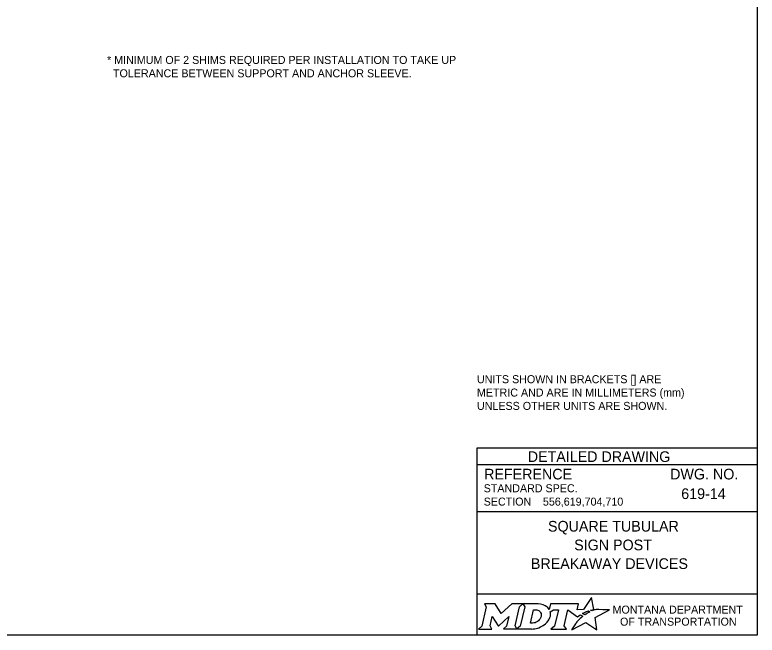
# Model space of a CAD drawing. Extents: x 49940 to 50043, y 49986 to 50011.
# Drawn here: x 50011.19 to 50016.75, y 49987.8 to 49992.45 of the extents above; entities that cross this region are included whole.
import ezdxf

# ---------------------------------------------------------------- set-up
doc = ezdxf.new("R2010")
doc.units = 0
for name, color, linetype in [('Default', 7, 'Continuous'), ('Level 1', 7, 'Continuous'), ('Level 2', 7, 'Continuous'), ('Level 5', 7, 'Continuous')]:
    doc.layers.add(name, color=color, linetype=linetype)

msp = doc.modelspace()

# ---------------------------------------------------------------- linework, layer by layer
at = {"layer": 'Default'}
for points in [[(50015.5126, 49987.9811), (50015.5023, 49987.9867), (50015.5139, 49987.9895), (50015.5255, 49987.9915), (50015.5081, 49988.0816), (50015.4486, 49987.9903), (50015.4013, 49987.9896), (50015.4116, 49988.0337), (50015.2024, 49988.0338), (50015.1923, 49987.9913), (50015.1865, 49987.9996)], [(50014.7056, 49988.0338), (50014.7197, 49988.0104), (50014.6862, 49987.8671), (50014.6605, 49987.8446), (50014.7621, 49987.8446), (50014.7486, 49987.8674), (50014.7648, 49987.9375), (50014.8085, 49987.8685), (50014.8138, 49987.8685), (50014.8889, 49987.938), (50014.8725, 49987.8669), (50014.8478, 49987.8449), (50014.9494, 49987.8449), (50014.9356, 49987.8682), (50014.9688, 49988.0106)], [(50014.9688, 49988.0106), (50014.9941, 49988.0338), (50014.9117, 49988.0338), (50014.8321, 49987.9608), (50014.7876, 49988.0335), (50014.7056, 49988.0338)], [(50015.1077, 49988.0338), (50014.9941, 49988.0338), (50015.0088, 49988.0109), (50014.9749, 49987.8671), (50014.9494, 49987.8449), (50015.06, 49987.8449)], [(50015.1317, 49987.9471), (50015.1305, 49987.939), (50015.1273, 49987.9297), (50015.1231, 49987.9215), (50015.1175, 49987.914), (50015.111, 49987.9071), (50015.1031, 49987.9008), (50015.0948, 49987.8961), (50015.0857, 49987.8922), (50015.0766, 49987.8899), (50015.0674, 49987.889), (50015.0515, 49987.889), (50015.0751, 49987.989), (50015.0911, 49987.989), (50015.0987, 49987.9884), (50015.1063, 49987.9865), (50015.1129, 49987.9835), (50015.119, 49987.9793), (50015.1238, 49987.9743), (50015.1275, 49987.9683), (50015.1302, 49987.9621), (50015.1318, 49987.9547), (50015.1318, 49987.9517), (50015.1317, 49987.9471)], [(50015.1991, 49987.9747), (50015.2237, 49987.9878), (50015.2606, 49987.9878), (50015.232, 49987.8673), (50015.2045, 49987.8446), (50015.3207, 49987.8446), (50015.3037, 49987.8675), (50015.3319, 49987.9877), (50015.4032, 49987.936), (50015.4243, 49987.9511), (50015.444, 49987.9402)], [(50015.3882, 49987.8843), (50015.3729, 49987.8599), (50015.3682, 49987.8524), (50015.3624, 49987.8438), (50015.3601, 49987.8395), (50015.4654, 49987.8926), (50015.5493, 49987.8375), (50015.5362, 49987.9302), (50015.6431, 49987.9886), (50015.5938, 49987.9894), (50015.5637, 49987.9898), (50015.5429, 49987.9901), (50015.5361, 49987.9886), (50015.5312, 49987.9874), (50015.5228, 49987.9851), (50015.5126, 49987.9811)], [(50015.4622, 49987.9535), (50015.4598, 49987.9518), (50015.4415, 49987.9614), (50015.4518, 49987.9671), (50015.4559, 49987.9693), (50015.4645, 49987.9733), (50015.4702, 49987.9759), (50015.4781, 49987.9789), (50015.4854, 49987.9816), (50015.4972, 49987.9742), (50015.4932, 49987.9721), (50015.4886, 49987.9696), (50015.4844, 49987.9674), (50015.4794, 49987.9645), (50015.4775, 49987.9634), (50015.4748, 49987.9618), (50015.4723, 49987.9604), (50015.47, 49987.9588), (50015.4674, 49987.957), (50015.4647, 49987.9552), (50015.4622, 49987.9535)], [(50015.4021, 49987.9004), (50015.4021, 49987.9004)], [(50015.1057, 49987.8522), (50015.1141, 49987.8548), (50015.1271, 49987.8602), (50015.1475, 49987.8712)]]:
    msp.add_lwpolyline(points, dxfattribs=at)
for centre, radius, start, end in [((50015.1308, 49987.9554), 0.0709, 339.5329, 15.8582), ((50015.0868, 49987.9727), 0.1183, 300.9103, 339.1383)]:
    msp.add_arc(centre, radius, start, end, dxfattribs=at)
for centre, major_axis, ratio, start_param, end_param in [((50015.1056, 49987.9864), (0.0834, -0.0037), 0.568097, 0.61298, 1.570796), ((50015.1612, 49987.9937), (0.0361, -0.0295), 0.469099, 1.225588, 1.570796), ((50015.3952, 49987.8923), (-0.00694, -0.00806), 0.008222, 0, 3.137361), ((50015.4119, 49987.9106), (-0.0098, -0.0102), 0.016458, 3.141593, 6.279097), ((50015.4329, 49987.9305), (-0.0112, -0.0097), 0.021651, 3.157348, 6.283185), ((50015.0603, 49987.9932), (0, 0.1484), 0.987302, 3.139398, 3.456847)]:
    msp.add_ellipse(centre, major_axis=major_axis, ratio=ratio, start_param=start_param, end_param=end_param, dxfattribs=at)
at = {"layer": 'Level 1'}
msp.add_lwpolyline([(49999.3835, 49998.9992), (50016.7501, 49998.9992), (50016.7501, 49987.7988), (49999.3835, 49987.7988)], close=True, dxfattribs=at)
at = {"layer": 'Level 5'}
for p, q in [((50016.7501, 49989.1988), (50014.6501, 49989.1988)), ((50014.6501, 49989.1988), (50014.6501, 49987.7988)), ((50016.7501, 49989.0738), (50014.6501, 49989.0738)), ((50016.3862, 49988.8587), (50016.3862, 49988.8587)), ((50015.1444, 49988.7993), (50015.1444, 49988.7993)), ((50016.7501, 49988.7238), (50014.6501, 49988.7238)), ((50015.7001, 49988.4747), (50015.7001, 49988.4747)), ((50016.7501, 49988.1057), (50014.6501, 49988.1057))]:
    msp.add_line(p, q, dxfattribs=at)

# ---------------------------------------------------------------- texts
at = {"layer": 'Default'}
for s, p in [('MONTANA DEPARTMENT', (50015.6663, 49987.96)), ('OF TRANSPORTATION', (50015.7225, 49987.87))]:
    msp.add_text(s, height=0.06, dxfattribs=at).set_placement(p)
at = {"layer": 'Level 2'}
for s, height, p in [('* MINIMUM OF 2 SHIMS REQUIRED PER INSTALLATION TO TAKE UP   ', 0.06, (50011.8777, 49992.0786)), ('  TOLERANCE BETWEEN SUPPORT AND ANCHOR SLEEVE.', 0.06, (50011.8777, 49991.9786)), ('UNITS SHOWN IN BRACKETS [] ARE ', 0.06, (50014.6501, 49989.6865)), ('METRIC AND ARE IN MILLIMETERS (mm) ', 0.06, (50014.6501, 49989.5865)), ('UNLESS OTHER UNITS ARE SHOWN.', 0.06, (50014.6501, 49989.4865)), ('619-14', 0.08, (50016.1811, 49988.8187)), ('556,619,704,710', 0.06, (50015.1444, 49988.7693)), ('SQUARE TUBULAR', 0.08, (50015.1825, 49988.5747)), ('SIGN POST', 0.08, (50015.3788, 49988.4347)), ('BREAKAWAY DEVICES', 0.08, (50015.0543, 49988.2947))]:
    msp.add_text(s, height=height, dxfattribs=at).set_placement(p)
at = {"layer": 'Level 5'}
for s, height, p in [('DETAILED DRAWING', 0.0799, (50015.0311, 49989.0963)), ('REFERENCE', 0.08, (50014.7037, 49988.9654)), ('DWG. NO.', 0.08, (50016.0979, 49988.9654)), ('STANDARD SPEC.', 0.06, (50014.7004, 49988.8694)), ('SECTION', 0.06, (50014.7004, 49988.7694))]:
    msp.add_text(s, height=height, dxfattribs=at).set_placement(p)

doc.saveas('drawing.dxf')
